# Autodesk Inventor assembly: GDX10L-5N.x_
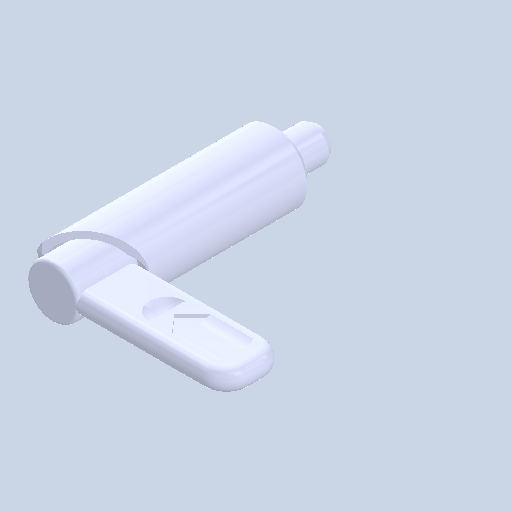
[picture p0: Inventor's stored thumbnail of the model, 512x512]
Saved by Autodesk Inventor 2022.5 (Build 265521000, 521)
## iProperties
Created: 2024-06
Part Number: GDX10L-5N.x_
Document SubType Name: Assembly
Designer: ImaoCorp
Author: ImaoCorp
Sending System: SOLIDWORKS 2022-2022290
MC: AMD64
MC_MODEL: Intel64 Family 6 Model 60 Stepping 3, GenuineIntel
OS: Windows_NT
FRU: Parasolid Version 33.1, build 260,  4-25-2022
FORMAT: text
GUISE: transmit
KEY: FILEGDX10L-5N.x_t
DATE: Wed Jun 12 09:31:14 2024
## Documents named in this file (3)
- Y:\5.更新分\2024年対応\xxxx_GDX\データ_imao品番\gdx10l-5n\GDX10L-5N.x_.iam
- Y:\5.更新分\2024年対応\xxxx_GDX\データ_imao品番\gdx10l-5n\GDX10L-5N_01.ipt
- Y:\5.更新分\2024年対応\xxxx_GDX\データ_imao品番\gdx10l-5n\GDX10L-5N_02.ipt
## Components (2 placed, 2 different names)
1. GDX10L-5N_01
2. GDX10L-5N_02
